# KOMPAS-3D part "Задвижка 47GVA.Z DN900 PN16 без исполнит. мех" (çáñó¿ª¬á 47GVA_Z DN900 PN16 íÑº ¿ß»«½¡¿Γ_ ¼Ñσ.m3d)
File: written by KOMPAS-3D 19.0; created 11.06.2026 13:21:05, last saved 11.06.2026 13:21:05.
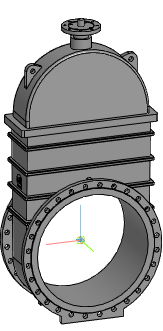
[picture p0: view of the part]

Document properties: Автор: Евгений; Полное имя файла: Z:\3.Личные\kachalov\001_3d для проектировщиков\2.2 Тип 47GVA, 47GVA.Z\_stp\_stp_Задвижка 47GVA.Z DN350-DN1200 без исп.мех\Задвижка 47GVA_Z DN900 PN16 без исполнит_ мех.m3d

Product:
- Part/product: Задвижка 47GVA.Z DN900 PN16 без исполнит. мех

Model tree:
1. Операция без истории:1  (labels: Задвижка 47GVA.Z DN900 PN16 без исполнит. мех)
